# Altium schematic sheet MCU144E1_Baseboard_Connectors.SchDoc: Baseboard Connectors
size 431 x 279 mm; DrawnBy: Gustavo Martinez; DocumentNumber: 10; SheetNumber: 6; SheetTotal: 8; PageSetup: Record=PageOptions¦CenterHorizontal=True¦CenterVertical=True¦PrintScale=1.00¦XCorrection=1.00¦YCorrection=1.00¦PrintKind=0¦BorderSize=5000000¦LeftOffset=0¦BottomOffset=0¦Orientation=2¦PaperLength=1000¦PaperWidth=1000¦Scale=100¦PaperSource=15¦PrintQuality=600¦MediaType=1¦DitherType=10¦PaperKind=Letter¦PrintScaleMode=1
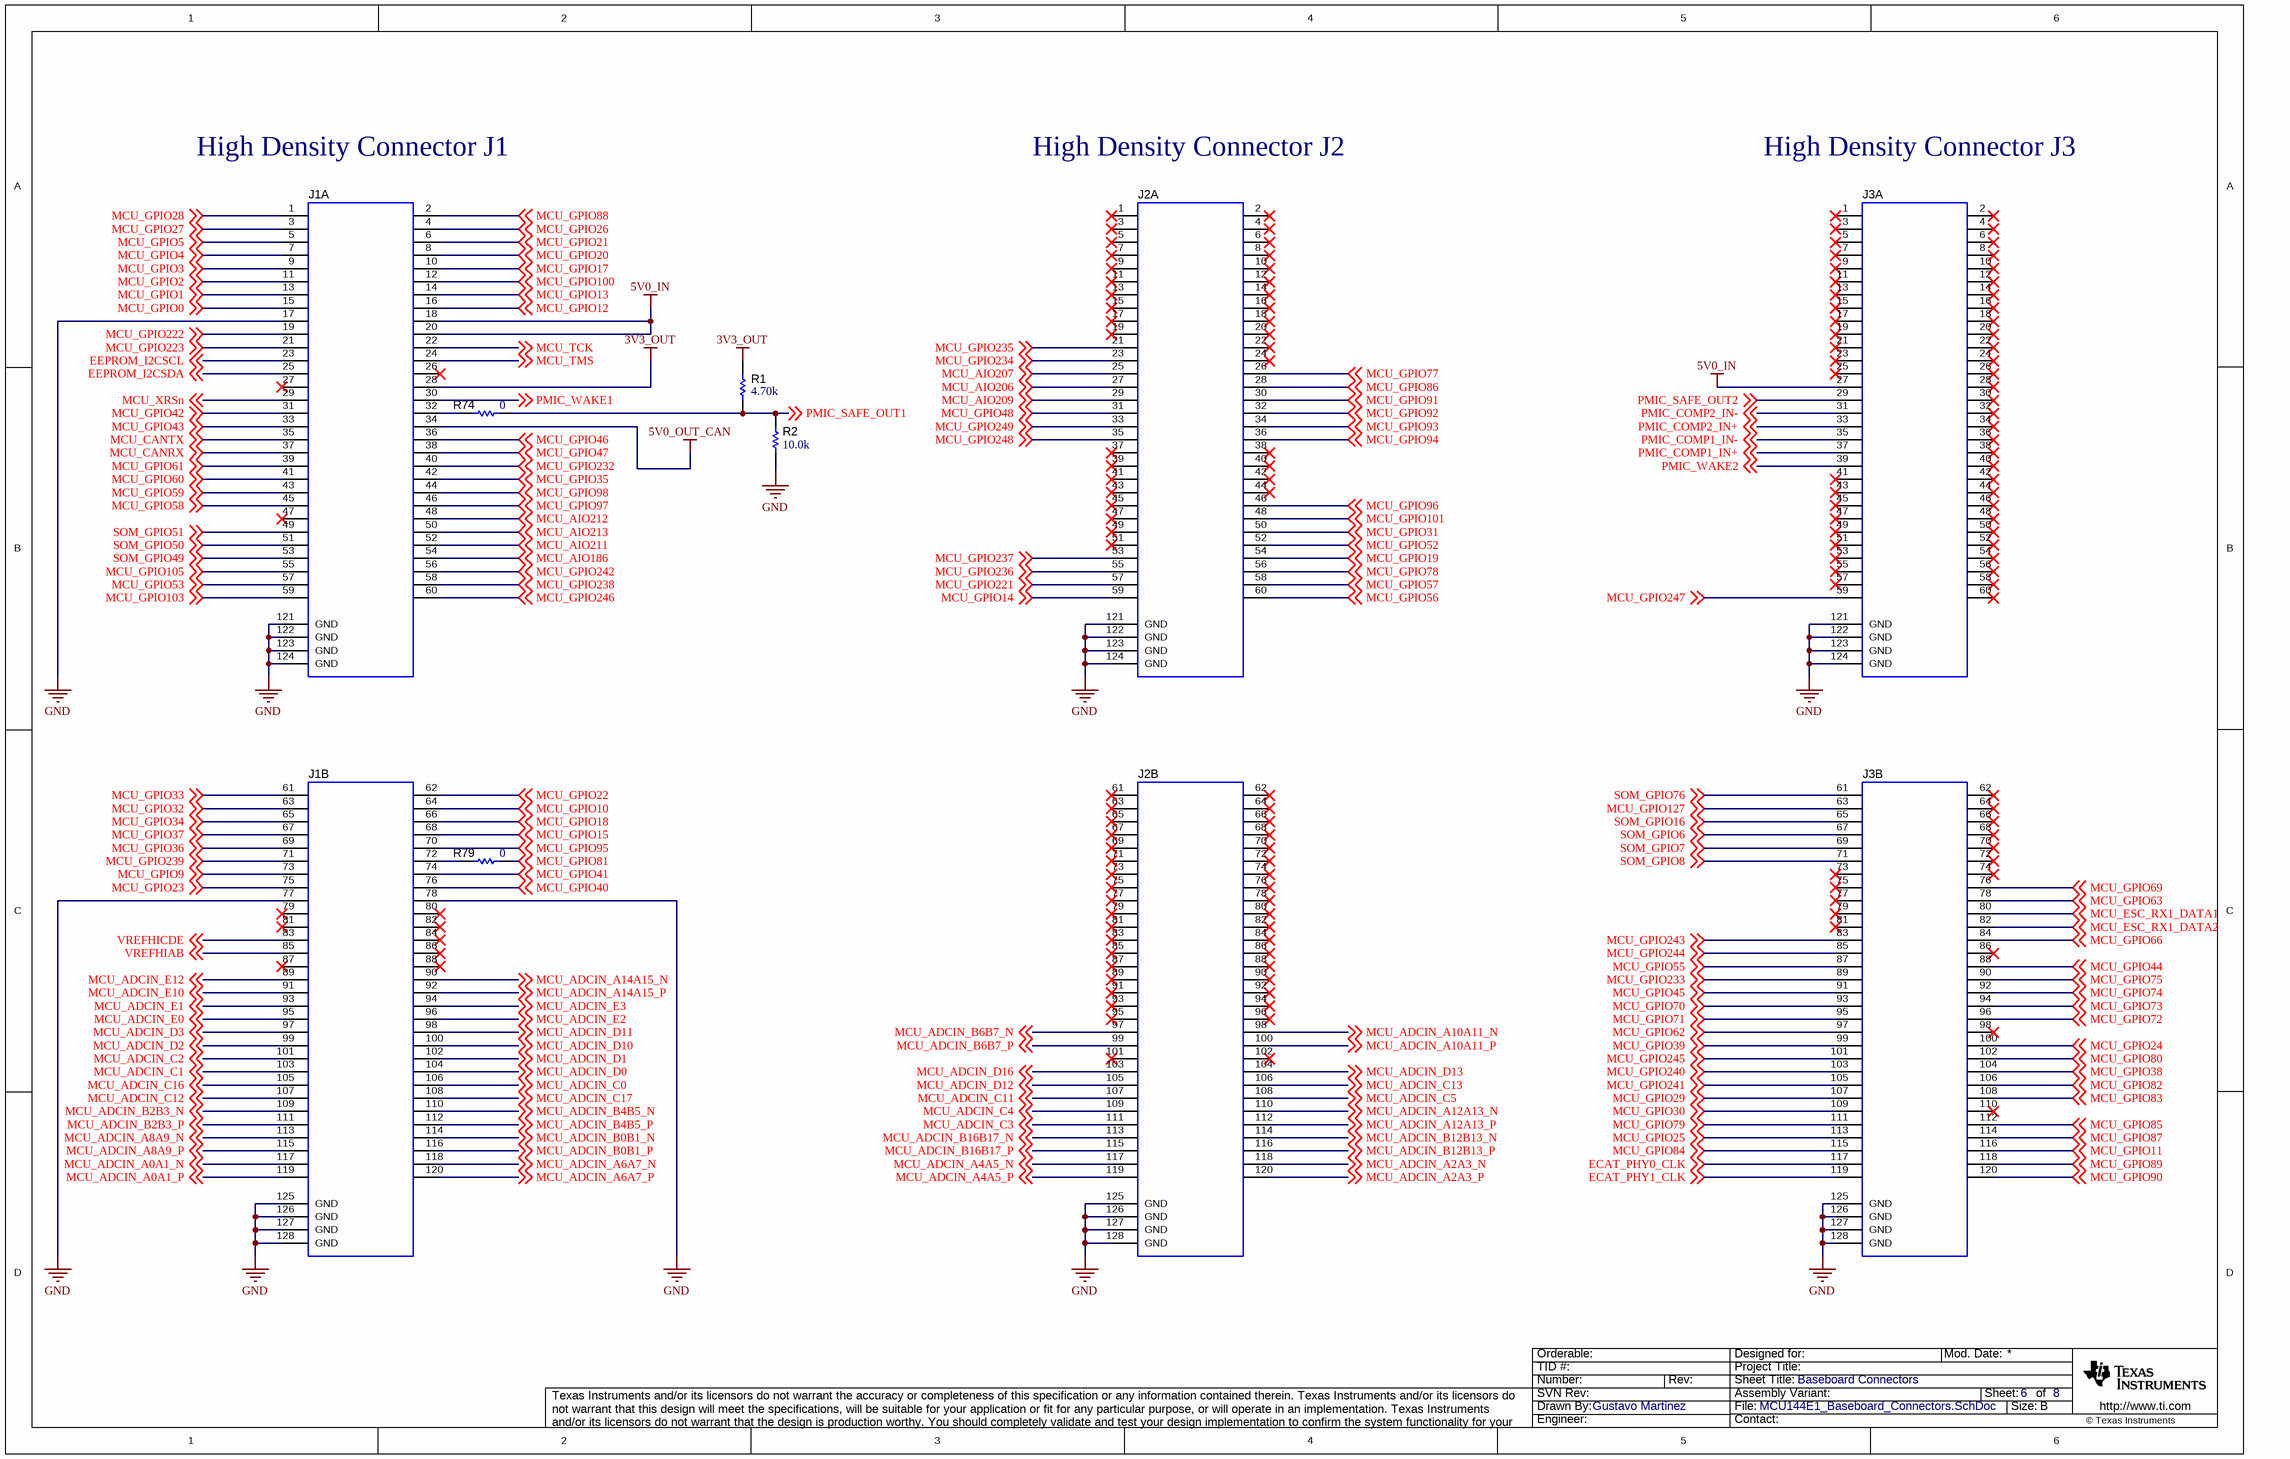
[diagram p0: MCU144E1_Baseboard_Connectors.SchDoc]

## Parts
J1  QSH-060-01-L-D-A  [CONN_QSH-060-01-L-D-A]  (value not drawn)  (parts A,B of 2)
J2  QSH-060-01-L-D-A  [CONN_QSH-060-01-L-D-A]  (value not drawn)  (parts A,B of 2)
J3  QSH-060-01-L-D-A  [CONN_QSH-060-01-L-D-A]  (value not drawn)  (parts A,B of 2)
R1  value 4.70k  [0402]  (hidden comment: CRG0402F4K7)
R2  value 10.0k  [0402]  (hidden comment: AC0402FR-0710KL)
R74  ValueDisplayed: 0  [0402]  (hidden comment: CRCW04020000Z0ED)
R79  ValueDisplayed: 0  [0402]  (hidden comment: CRCW04020000Z0ED)

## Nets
3V3_OUT: J1.28 R1.2
5V0_IN: J1.18 J1.20 J3.27
5V0_OUT_CAN: J1.34
GND: J1.17 J1.77 J1.78 J1.121(GND) J1.122(GND) J1.123(GND) J1.124(GND) J1.125(GND) J1.126(GND) J1.127(GND) J1.128(GND) J2.121(GND) J2.122(GND) J2.123(GND) J2.124(GND) J2.125(GND) J2.126(GND) J2.127(GND) J2.128(GND) J3.121(GND) J3.122(GND) J3.123(GND) J3.124(GND) J3.125(GND) J3.126(GND) J3.127(GND) J3.128(GND) R2.1
ECAT_PHY0_CLK: J3.117 ; off-sheet ECAT_PHY0_CLK
ECAT_PHY1_CLK: J3.119 ; off-sheet ECAT_PHY1_CLK
EEPROM_I2CSCL: J1.23 ; off-sheet EEPROM_I2CSCL
EEPROM_I2CSDA: J1.25 ; off-sheet EEPROM_I2CSDA
MCU_ADCIN_A0A1_N: J1.117 ; off-sheet MCU_ADCIN_A0A1_N
MCU_ADCIN_A0A1_P: J1.119 ; off-sheet MCU_ADCIN_A0A1_P
MCU_ADCIN_A2A3_N: J2.118 ; off-sheet MCU_ADCIN_A2A3_N
MCU_ADCIN_A2A3_P: J2.120 ; off-sheet MCU_ADCIN_A2A3_P
MCU_ADCIN_A4A5_N: J2.117 ; off-sheet MCU_ADCIN_A4A5_N
MCU_ADCIN_A4A5_P: J2.119 ; off-sheet MCU_ADCIN_A4A5_P
MCU_ADCIN_A6A7_N: J1.118 ; off-sheet MCU_ADCIN_A6A7_N
MCU_ADCIN_A6A7_P: J1.120 ; off-sheet MCU_ADCIN_A6A7_P
MCU_ADCIN_A8A9_N: J1.113 ; off-sheet MCU_ADCIN_A8A9_N
MCU_ADCIN_A8A9_P: J1.115 ; off-sheet MCU_ADCIN_A8A9_P
MCU_ADCIN_A10A11_N: J2.98 ; off-sheet MCU_ADCIN_A10A11_N
MCU_ADCIN_A10A11_P: J2.100 ; off-sheet MCU_ADCIN_A10A11_P
MCU_ADCIN_A12A13_N: J2.110 ; off-sheet MCU_ADCIN_A12A13_N
MCU_ADCIN_A12A13_P: J2.112 ; off-sheet MCU_ADCIN_A12A13_P
MCU_ADCIN_A14A15_N: J1.90 ; off-sheet MCU_ADCIN_A14A15_N
MCU_ADCIN_A14A15_P: J1.92 ; off-sheet MCU_ADCIN_A14A15_P
MCU_ADCIN_B0B1_N: J1.114 ; off-sheet MCU_ADCIN_B0B1_N
MCU_ADCIN_B0B1_P: J1.116 ; off-sheet MCU_ADCIN_B0B1_P
MCU_ADCIN_B2B3_N: J1.109 ; off-sheet MCU_ADCIN_B2B3_N
MCU_ADCIN_B2B3_P: J1.111 ; off-sheet MCU_ADCIN_B2B3_P
MCU_ADCIN_B4B5_N: J1.110 ; off-sheet MCU_ADCIN_B4B5_N
MCU_ADCIN_B4B5_P: J1.112 ; off-sheet MCU_ADCIN_B4B5_P
MCU_ADCIN_B6B7_N: J2.97 ; off-sheet MCU_ADCIN_B6B7_N
MCU_ADCIN_B6B7_P: J2.99 ; off-sheet MCU_ADCIN_B6B7_P
MCU_ADCIN_B12B13_N: J2.114 ; off-sheet MCU_ADCIN_B12B13_N
MCU_ADCIN_B12B13_P: J2.116 ; off-sheet MCU_ADCIN_B12B13_P
MCU_ADCIN_B16B17_N: J2.113 ; off-sheet MCU_ADCIN_B16B17_N
MCU_ADCIN_B16B17_P: J2.115 ; off-sheet MCU_ADCIN_B16B17_P
MCU_ADCIN_C0: J1.106 ; off-sheet MCU_ADCIN_C0
MCU_ADCIN_C1: J1.103 ; off-sheet MCU_ADCIN_C1
MCU_ADCIN_C2: J1.101 ; off-sheet MCU_ADCIN_C2
MCU_ADCIN_C3: J2.111 ; off-sheet MCU_ADCIN_C3
MCU_ADCIN_C4: J2.109 ; off-sheet MCU_ADCIN_C4
MCU_ADCIN_C5: J2.108 ; off-sheet MCU_ADCIN_C5
MCU_ADCIN_C11: J2.107 ; off-sheet MCU_ADCIN_C11
MCU_ADCIN_C12: J1.107 ; off-sheet MCU_ADCIN_C12
MCU_ADCIN_C13: J2.106 ; off-sheet MCU_ADCIN_C13
MCU_ADCIN_C16: J1.105 ; off-sheet MCU_ADCIN_C16
MCU_ADCIN_C17: J1.108 ; off-sheet MCU_ADCIN_C17
MCU_ADCIN_D0: J1.104 ; off-sheet MCU_ADCIN_D0
MCU_ADCIN_D1: J1.102 ; off-sheet MCU_ADCIN_D1
MCU_ADCIN_D2: J1.99 ; off-sheet MCU_ADCIN_D2
MCU_ADCIN_D3: J1.97 ; off-sheet MCU_ADCIN_D3
MCU_ADCIN_D10: J1.100 ; off-sheet MCU_ADCIN_D10
MCU_ADCIN_D11: J1.98 ; off-sheet MCU_ADCIN_D11
MCU_ADCIN_D12: J2.105 ; off-sheet MCU_ADCIN_D12
MCU_ADCIN_D13: J2.104 ; off-sheet MCU_ADCIN_D13
MCU_ADCIN_D16: J2.103 ; off-sheet MCU_ADCIN_D16
MCU_ADCIN_E0: J1.95 ; off-sheet MCU_ADCIN_E0
MCU_ADCIN_E1: J1.93 ; off-sheet MCU_ADCIN_E1
MCU_ADCIN_E2: J1.96 ; off-sheet MCU_ADCIN_E2
MCU_ADCIN_E3: J1.94 ; off-sheet MCU_ADCIN_E3
MCU_ADCIN_E10: J1.91 ; off-sheet MCU_ADCIN_E10
MCU_ADCIN_E12: J1.89 ; off-sheet MCU_ADCIN_E12
MCU_AIO186: J1.54 ; off-sheet MCU_AIO186
MCU_AIO206: J2.27 ; off-sheet MCU_AIO206
MCU_AIO207: J2.25 ; off-sheet MCU_AIO207
MCU_AIO209: J2.29 ; off-sheet MCU_AIO209
MCU_AIO211: J1.52 ; off-sheet MCU_AIO211
MCU_AIO212: J1.48 ; off-sheet MCU_AIO212
MCU_AIO213: J1.50 ; off-sheet MCU_AIO213
MCU_CANRX: J1.37 ; off-sheet MCU_CANRX
MCU_CANTX: J1.35 ; off-sheet MCU_CANTX
MCU_ESC_RX1_DATA1: J3.80 ; off-sheet MCU_ESC_RX1_DATA1
MCU_ESC_RX1_DATA2: J3.82 ; off-sheet MCU_ESC_RX1_DATA2
MCU_GPIO0: J1.15 ; off-sheet MCU_GPIO0
MCU_GPIO1: J1.13 ; off-sheet MCU_GPIO1
MCU_GPIO2: J1.11 ; off-sheet MCU_GPIO2
MCU_GPIO3: J1.9 ; off-sheet MCU_GPIO3
MCU_GPIO4: J1.7 ; off-sheet MCU_GPIO4
MCU_GPIO5: J1.5 ; off-sheet MCU_GPIO5
MCU_GPIO9: J1.73 ; off-sheet MCU_GPIO9
MCU_GPIO10: J1.64 ; off-sheet MCU_GPIO10
MCU_GPIO11: J3.116 ; off-sheet MCU_GPIO11
MCU_GPIO12: J1.16 ; off-sheet MCU_GPIO12
MCU_GPIO13: J1.14 ; off-sheet MCU_GPIO13
MCU_GPIO14: J2.59 ; off-sheet MCU_GPIO14
MCU_GPIO15: J1.68 ; off-sheet MCU_GPIO15
MCU_GPIO17: J1.10 ; off-sheet MCU_GPIO17
MCU_GPIO18: J1.66 ; off-sheet MCU_GPIO18
MCU_GPIO19: J2.54 ; off-sheet MCU_GPIO19
MCU_GPIO20: J1.8 ; off-sheet MCU_GPIO20
MCU_GPIO21: J1.6 ; off-sheet MCU_GPIO21
MCU_GPIO22: J1.62 ; off-sheet MCU_GPIO22
MCU_GPIO23: J1.75 ; off-sheet MCU_GPIO23
MCU_GPIO24: J3.100 ; off-sheet MCU_GPIO24
MCU_GPIO25: J3.113 ; off-sheet MCU_GPIO25
MCU_GPIO26: J1.4 ; off-sheet MCU_GPIO26
MCU_GPIO27: J1.3 ; off-sheet MCU_GPIO27
MCU_GPIO28: J1.1 ; off-sheet MCU_GPIO28
MCU_GPIO29: J3.107 ; off-sheet MCU_GPIO29
MCU_GPIO30: J3.109 ; off-sheet MCU_GPIO30
MCU_GPIO31: J2.50 ; off-sheet MCU_GPIO31
MCU_GPIO32: J1.63 ; off-sheet MCU_GPIO32
MCU_GPIO33: J1.61 ; off-sheet MCU_GPIO33
MCU_GPIO34: J1.65 ; off-sheet MCU_GPIO34
MCU_GPIO35: J1.42 ; off-sheet MCU_GPIO35
MCU_GPIO36: J1.69 ; off-sheet MCU_GPIO36
MCU_GPIO37: J1.67 ; off-sheet MCU_GPIO37
MCU_GPIO38: J3.104 ; off-sheet MCU_GPIO38
MCU_GPIO39: J3.99 ; off-sheet MCU_GPIO39
MCU_GPIO40: J1.76 ; off-sheet MCU_GPIO40
MCU_GPIO41: J1.74 ; off-sheet MCU_GPIO41
MCU_GPIO42: J1.31 ; off-sheet MCU_GPIO42
MCU_GPIO43: J1.33 ; off-sheet MCU_GPIO43
MCU_GPIO44: J3.88 ; off-sheet MCU_GPIO44
MCU_GPIO45: J3.91 ; off-sheet MCU_GPIO45
MCU_GPIO46: J1.36 ; off-sheet MCU_GPIO46
MCU_GPIO47: J1.38 ; off-sheet MCU_GPIO47
MCU_GPIO48: J2.31 ; off-sheet MCU_GPIO48
MCU_GPIO52: J2.52 ; off-sheet MCU_GPIO52
MCU_GPIO53: J1.57 ; off-sheet MCU_GPIO53
MCU_GPIO55: J3.87 ; off-sheet MCU_GPIO55
MCU_GPIO56: J2.60 ; off-sheet MCU_GPIO56
MCU_GPIO57: J2.58 ; off-sheet MCU_GPIO57
MCU_GPIO58: J1.45 ; off-sheet MCU_GPIO58
MCU_GPIO59: J1.43 ; off-sheet MCU_GPIO59
MCU_GPIO60: J1.41 ; off-sheet MCU_GPIO60
MCU_GPIO61: J1.39 ; off-sheet MCU_GPIO61
MCU_GPIO62: J3.97 ; off-sheet MCU_GPIO62
MCU_GPIO63: J3.78 ; off-sheet MCU_GPIO63
MCU_GPIO66: J3.84 ; off-sheet MCU_GPIO66
MCU_GPIO69: J3.76 ; off-sheet MCU_GPIO69
MCU_GPIO70: J3.93 ; off-sheet MCU_GPIO70
MCU_GPIO71: J3.95 ; off-sheet MCU_GPIO71
MCU_GPIO72: J3.96 ; off-sheet MCU_GPIO72
MCU_GPIO73: J3.94 ; off-sheet MCU_GPIO73
MCU_GPIO74: J3.92 ; off-sheet MCU_GPIO74
MCU_GPIO75: J3.90 ; off-sheet MCU_GPIO75
MCU_GPIO77: J2.26 ; off-sheet MCU_GPIO77
MCU_GPIO78: J2.56 ; off-sheet MCU_GPIO78
MCU_GPIO79: J3.111 ; off-sheet MCU_GPIO79
MCU_GPIO80: J3.102 ; off-sheet MCU_GPIO80
MCU_GPIO81: R79.2 ; off-sheet MCU_GPIO81
MCU_GPIO82: J3.106 ; off-sheet MCU_GPIO82
MCU_GPIO83: J3.108 ; off-sheet MCU_GPIO83
MCU_GPIO84: J3.115 ; off-sheet MCU_GPIO84
MCU_GPIO85: J3.112 ; off-sheet MCU_GPIO85
MCU_GPIO86: J2.28 ; off-sheet MCU_GPIO86
MCU_GPIO87: J3.114 ; off-sheet MCU_GPIO87
MCU_GPIO88: J1.2 ; off-sheet MCU_GPIO88
MCU_GPIO89: J3.118 ; off-sheet MCU_GPIO89
MCU_GPIO90: J3.120 ; off-sheet MCU_GPIO90
MCU_GPIO91: J2.30 ; off-sheet MCU_GPIO91
MCU_GPIO92: J2.32 ; off-sheet MCU_GPIO92
MCU_GPIO93: J2.34 ; off-sheet MCU_GPIO93
MCU_GPIO94: J2.36 ; off-sheet MCU_GPIO94
MCU_GPIO95: J1.70 ; off-sheet MCU_GPIO95
MCU_GPIO96: J2.46 ; off-sheet MCU_GPIO96
MCU_GPIO97: J1.46 ; off-sheet MCU_GPIO97
MCU_GPIO98: J1.44 ; off-sheet MCU_GPIO98
MCU_GPIO100: J1.12 ; off-sheet MCU_GPIO100
MCU_GPIO101: J2.48 ; off-sheet MCU_GPIO101
MCU_GPIO103: J1.59 ; off-sheet MCU_GPIO103
MCU_GPIO105: J1.55 ; off-sheet MCU_GPIO105
MCU_GPIO127: J3.63 ; off-sheet MCU_GPIO127
MCU_GPIO221: J2.57 ; off-sheet MCU_GPIO221
MCU_GPIO222: J1.19 ; off-sheet MCU_GPIO222
MCU_GPIO223: J1.21 ; off-sheet MCU_GPIO223
MCU_GPIO232: J1.40 ; off-sheet MCU_GPIO232
MCU_GPIO233: J3.89 ; off-sheet MCU_GPIO233
MCU_GPIO234: J2.23 ; off-sheet MCU_GPIO234
MCU_GPIO235: J2.21 ; off-sheet MCU_GPIO235
MCU_GPIO236: J2.55 ; off-sheet MCU_GPIO236
MCU_GPIO237: J2.53 ; off-sheet MCU_GPIO237
MCU_GPIO238: J1.58 ; off-sheet MCU_GPIO238
MCU_GPIO239: J1.71 ; off-sheet MCU_GPIO239
MCU_GPIO240: J3.103 ; off-sheet MCU_GPIO240
MCU_GPIO241: J3.105 ; off-sheet MCU_GPIO241
MCU_GPIO242: J1.56 ; off-sheet MCU_GPIO242
MCU_GPIO243: J3.83 ; off-sheet MCU_GPIO243
MCU_GPIO244: J3.85 ; off-sheet MCU_GPIO244
MCU_GPIO245: J3.101 ; off-sheet MCU_GPIO245
MCU_GPIO246: J1.60 ; off-sheet MCU_GPIO246
MCU_GPIO247: J3.59 ; off-sheet MCU_GPIO247
MCU_GPIO248: J2.35 ; off-sheet MCU_GPIO248
MCU_GPIO249: J2.33 ; off-sheet MCU_GPIO249
MCU_TCK: J1.22 ; off-sheet MCU_TCK
MCU_TMS: J1.24 ; off-sheet MCU_TMS
MCU_XRSn: J1.29 ; off-sheet MCU_XRSn
PMIC_COMP1_IN+: J3.37 ; off-sheet PMIC_COMP1_IN+
PMIC_COMP1_IN-: J3.35 ; off-sheet PMIC_COMP1_IN-
PMIC_COMP2_IN+: J3.33 ; off-sheet PMIC_COMP2_IN+
PMIC_COMP2_IN-: J3.31 ; off-sheet PMIC_COMP2_IN-
PMIC_SAFE_OUT1: R1.1 R2.2 R74.2 ; off-sheet PMIC_SAFE_OUT1
PMIC_SAFE_OUT2: J3.29 ; off-sheet PMIC_SAFE_OUT2
PMIC_WAKE1: J1.30 ; off-sheet PMIC_WAKE1
PMIC_WAKE2: J3.39 ; off-sheet PMIC_WAKE2
SOM_GPIO6: J3.67 ; off-sheet SOM_GPIO6
SOM_GPIO7: J3.69 ; off-sheet SOM_GPIO7
SOM_GPIO8: J3.71 ; off-sheet SOM_GPIO8
SOM_GPIO16: J3.65 ; off-sheet SOM_GPIO16
SOM_GPIO49: J1.53 ; off-sheet SOM_GPIO49
SOM_GPIO50: J1.51 ; off-sheet SOM_GPIO50
SOM_GPIO51: J1.49 ; off-sheet SOM_GPIO51
SOM_GPIO76: J3.61 ; off-sheet SOM_GPIO76
VREFHIAB: J1.85 ; off-sheet VREFHIAB
VREFHICDE: J1.83 ; off-sheet VREFHICDE
NetJ1_32: J1.32 R74.1
NetJ1_72: J1.72 R79.1

Not connected (* = marked no-connect by the designer): J1 26* 27* 47* 79* 80* 81* 82* 84* 86* 87* 88*; J2 1* 2* 3* 4* 5* 6* 7* 8* 9* 10* 11* 12* 13* 14* 15* 16* 17* 18* 19* 20* 22* 24* 37* 38* 39* 40* 41* 42* 43* 44* 45* 47* 49* 51* 61* 62* 63* 64* 65* 66* 67* 68* 69* 70* 71* 72* 73* 74* 75* 76* 77* 78* 79* 80* 81* 82* 83* 84* 85* 86* 87* 88* 89* 90* 91* 92* 93* 94* 95* 96* 101* 102*; J3 1* 2* 3* 4* 5* 6* 7* 8* 9* 10* 11* 12* 13* 14* 15* 16* 17* 18* 19* 20* 21* 22* 23* 24* 25* 26* 28* 30* 32* 34* 36* 38* 40* 41* 42* 43* 44* 45* 46* 47* 48* 49* 50* 51* 52* 53* 54* 55* 56* 57* 58* 60* 62* 64* 66* 68* 70* 72* 73* 74* 75* 77* 79* 81* 86* 98* 110*

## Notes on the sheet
- High Density Connector J1
- High Density Connector J2
- High Density Connector J3

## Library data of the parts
J1-J3 = CMP-0055973-1: Connector,  0.5mm, 60x2, SMT; Manufacturer: Samtec; CT: FALSE
R1 = CMP-0026631-1: RES, 4.70 k, 1%, 0.063 W, 0402; Manufacturer: TE Connectivity; Power_W: 63mW; TempCo: 100 ppm/C; Value_Code: 4k70; U/M: EA; Res_ohm: 4.7k; SizeX_mm: 1; SizeY_mm: 0.5; SizeZ_mm: 0.6; Value2: 0.063W; AEC Qualified: N; AEC Category: Q200
R2 = CMP-0077731-1: RES, 10.0 k, 1%, 0.063 W, AEC-Q200 Grade 0, 0402; Manufacturer: Yageo America; Power_W: 63mW; TempCo: 100 ppm/C; Value_Code: 10k0; U/M: EA; EIA_Code: E96; Res_ohm: 10k; SizeX_mm: 1.0; SizeY_mm: 0.5; SizeZ_mm: 0.6; Value2: 0.063W; AEC Qualified: Y; VDC_V: 50V; AEC Grade: 0; AEC Category: Q200
R74 R79 = CMP-0026822-3: RES, 0, 5%, 0.063 W, AEC-Q200 Grade 0, 0402; Manufacturer: Vishay-Dale; Power_W: 63mW; TempCo: 200 ppm/C; Value_Code: 0000; Value: 0; EIA_Code: E24; SizeX_mm: 1; SizeY_mm: 0.5; SizeZ_mm: 0.6; Value2: 0.063W; AEC Qualified: Y; VDC_V: 50V; AEC Category: Q200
